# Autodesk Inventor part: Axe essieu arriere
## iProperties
Created: 2002-04
Part Number: Axe essieu arriere
Material: Par défaut
Document SubType Name: Modélisation
Designer: Flavien MARTY
Control State: 0
Master: False
Checked Out: False
Shininess: 20.0
Length Units: 11269
Angle Units: 11279
Time Units: 11290
Mass Units: 11283
Length Display Precision: 3
Angle Display Precision: 2
Compacted: True
Density: 0.0
Volumn: 0.0
Area: 0.0
PropertySet Name: Model Information
Author: Flavien MARTY
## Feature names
1. Révolution1 [Revolution]
